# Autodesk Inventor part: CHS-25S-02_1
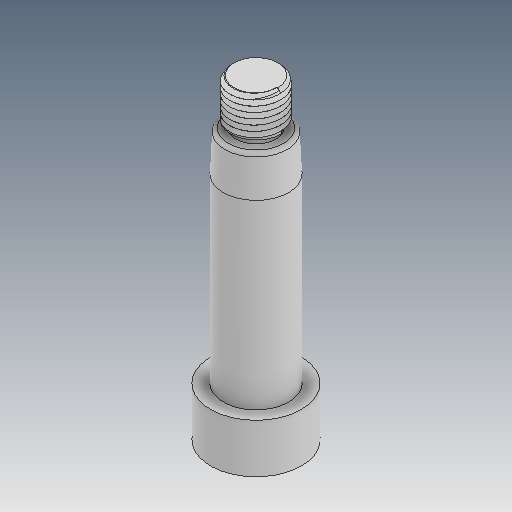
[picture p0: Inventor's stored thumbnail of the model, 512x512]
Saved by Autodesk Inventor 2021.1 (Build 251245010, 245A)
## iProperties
Created: 2019-04
Part Number: CHS-25S-02_1
Material: Ogólny
Document SubType Name: Modeling
Designer: user
Density: 1 g/cm^3
Appearance: Domyślna
Author: user
Revision Number: ÈÎºÎ
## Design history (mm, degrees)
feature "ÊäÈë1"
feature "ÊäÈë2"
node "Bryła1"
node "Bryła2"
